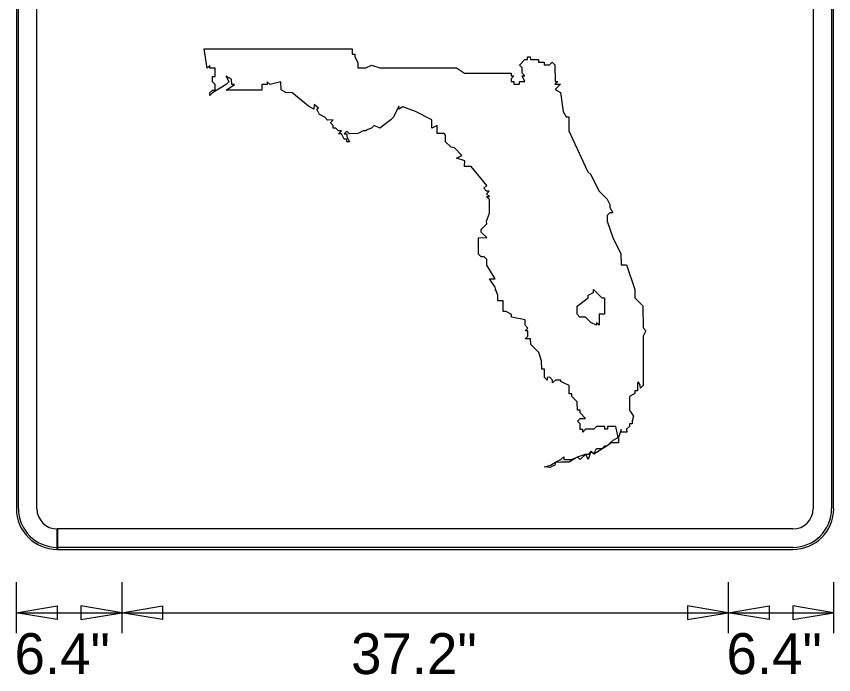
# Model space of a CAD drawing. Extents: x 17890628 to 17890844, y 17897693 to 17898031.
# Drawn here: x 17890743.68 to 17890757.02, y 17897935.63 to 17897946.37 of the extents above; entities that cross this region are included whole.
import ezdxf

# ---------------------------------------------------------------- set-up
doc = ezdxf.new("R2010")
doc.units = 0
doc.layers.add('GSColorFill', color=7, linetype='Continuous')
doc.layers.add('GSDims', color=7, linetype='Continuous')

msp = doc.modelspace()

# ---------------------------------------------------------------- linework, layer by layer
at = {"layer": 'GSColorFill'}
for p, q in [((17890743.684, 17897953.004), (17890743.684, 17897938.337)), ((17890743.684, 17897953.004), (17890743.684, 17897938.337)), ((17890743.684, 17897953.004), (17890743.684, 17897938.337)), ((17890743.717, 17897938.337), (17890743.717, 17897953.004)), ((17890744.017, 17897938.337), (17890744.017, 17897953.004)), ((17890756.684, 17897953.004), (17890756.684, 17897938.337)), ((17890756.984, 17897953.004), (17890756.984, 17897938.337)), ((17890757.017, 17897938.337), (17890757.017, 17897953.004)), ((17890757.017, 17897938.337), (17890757.017, 17897953.004)), ((17890757.017, 17897938.337), (17890757.017, 17897953.004)), ((17890746.75, 17897945.836), (17890749.163, 17897945.839)), ((17890746.794, 17897945.523), (17890746.75, 17897945.836)), ((17890749.163, 17897945.839), (17890749.163, 17897945.75)), ((17890749.163, 17897945.75), (17890749.208, 17897945.749)), ((17890749.208, 17897945.749), (17890749.207, 17897945.705)), ((17890749.207, 17897945.705), (17890749.252, 17897945.616)), ((17890751.89, 17897945.573), (17890751.979, 17897945.663)), ((17890751.979, 17897945.663), (17890752.023, 17897945.663)), ((17890752.023, 17897945.663), (17890752.024, 17897945.708)), ((17890752.024, 17897945.708), (17890752.068, 17897945.708)), ((17890752.068, 17897945.708), (17890752.069, 17897945.663)), ((17890752.069, 17897945.663), (17890752.203, 17897945.663)), ((17890752.203, 17897945.663), (17890752.203, 17897945.619)), ((17890752.203, 17897945.619), (17890752.293, 17897945.619)), ((17890752.293, 17897945.619), (17890752.293, 17897945.575)), ((17890752.381, 17897945.574), (17890752.426, 17897945.619)), ((17890752.426, 17897945.619), (17890752.471, 17897945.574)), ((17890746.839, 17897945.567), (17890746.794, 17897945.523)), ((17890746.838, 17897945.523), (17890746.839, 17897945.567)), ((17890746.928, 17897945.524), (17890746.838, 17897945.523)), ((17890746.928, 17897945.389), (17890746.928, 17897945.524)), ((17890749.252, 17897945.616), (17890749.252, 17897945.526)), ((17890749.252, 17897945.526), (17890749.387, 17897945.527)), ((17890749.387, 17897945.527), (17890749.477, 17897945.571)), ((17890749.477, 17897945.571), (17890749.611, 17897945.527)), ((17890749.611, 17897945.527), (17890750.862, 17897945.529)), ((17890750.862, 17897945.529), (17890750.996, 17897945.439)), ((17890751.935, 17897945.529), (17890751.89, 17897945.573)), ((17890751.935, 17897945.44), (17890751.935, 17897945.529)), ((17890752.293, 17897945.575), (17890752.381, 17897945.574)), ((17890752.471, 17897945.574), (17890752.472, 17897945.307)), ((17890746.884, 17897945.3), (17890746.883, 17897945.389)), ((17890746.883, 17897945.389), (17890746.928, 17897945.389)), ((17890747.196, 17897945.345), (17890747.107, 17897945.39)), ((17890747.107, 17897945.39), (17890747.152, 17897945.3)), ((17890750.996, 17897945.439), (17890751.756, 17897945.44)), ((17890751.756, 17897945.44), (17890751.756, 17897945.395)), ((17890751.756, 17897945.395), (17890751.801, 17897945.395)), ((17890751.801, 17897945.395), (17890751.756, 17897945.351)), ((17890751.979, 17897945.395), (17890751.935, 17897945.44)), ((17890751.979, 17897945.305), (17890751.935, 17897945.396)), ((17890751.935, 17897945.396), (17890751.979, 17897945.395)), ((17890746.928, 17897945.255), (17890746.884, 17897945.3)), ((17890747.107, 17897945.256), (17890746.884, 17897945.121)), ((17890746.929, 17897945.166), (17890746.928, 17897945.255)), ((17890747.152, 17897945.3), (17890747.107, 17897945.256)), ((17890747.108, 17897945.166), (17890747.241, 17897945.256)), ((17890747.197, 17897945.256), (17890747.196, 17897945.345)), ((17890747.241, 17897945.256), (17890747.197, 17897945.256)), ((17890747.778, 17897945.256), (17890747.688, 17897945.256)), ((17890747.688, 17897945.256), (17890747.689, 17897945.166)), ((17890747.822, 17897945.256), (17890747.777, 17897945.301)), ((17890747.777, 17897945.301), (17890747.778, 17897945.256)), ((17890748.001, 17897945.301), (17890747.822, 17897945.256)), ((17890748.002, 17897945.167), (17890748.001, 17897945.301)), ((17890751.756, 17897945.351), (17890751.756, 17897945.305)), ((17890751.756, 17897945.305), (17890751.801, 17897945.305)), ((17890751.801, 17897945.305), (17890751.801, 17897945.261)), ((17890751.801, 17897945.261), (17890751.89, 17897945.261)), ((17890751.89, 17897945.261), (17890751.891, 17897945.306)), ((17890751.891, 17897945.306), (17890751.979, 17897945.305)), ((17890752.516, 17897945.306), (17890752.471, 17897945.262)), ((17890752.471, 17897945.262), (17890752.561, 17897945.262)), ((17890752.472, 17897945.307), (17890752.516, 17897945.306)), ((17890752.561, 17897945.262), (17890752.472, 17897945.173)), ((17890746.839, 17897945.121), (17890746.884, 17897945.166)), ((17890746.884, 17897945.121), (17890746.839, 17897945.077)), ((17890746.839, 17897945.077), (17890746.839, 17897945.121)), ((17890746.884, 17897945.166), (17890746.929, 17897945.166)), ((17890747.689, 17897945.166), (17890747.108, 17897945.166)), ((17890748.092, 17897945.122), (17890748.002, 17897945.167)), ((17890748.18, 17897945.123), (17890748.092, 17897945.122)), ((17890748.449, 17897944.9), (17890748.18, 17897945.123)), ((17890752.472, 17897945.173), (17890752.561, 17897945.128)), ((17890752.561, 17897945.128), (17890752.607, 17897944.815)), ((17890748.539, 17897944.854), (17890748.449, 17897944.9)), ((17890748.542, 17897944.93), (17890748.539, 17897944.854)), ((17890748.612, 17897944.869), (17890748.542, 17897944.93)), ((17890748.583, 17897944.854), (17890748.612, 17897944.869)), ((17890748.627, 17897944.765), (17890748.583, 17897944.854)), ((17890749.924, 17897944.901), (17890749.835, 17897944.723)), ((17890749.924, 17897944.856), (17890749.924, 17897944.901)), ((17890749.988, 17897944.889), (17890749.924, 17897944.856)), ((17890750.193, 17897944.813), (17890749.988, 17897944.889)), ((17890748.718, 17897944.721), (17890748.627, 17897944.765)), ((17890748.762, 17897944.676), (17890748.718, 17897944.721)), ((17890749.835, 17897944.723), (17890749.791, 17897944.678)), ((17890750.461, 17897944.678), (17890750.193, 17897944.813)), ((17890752.607, 17897944.815), (17890752.651, 17897944.726)), ((17890752.651, 17897944.726), (17890752.696, 17897944.726)), ((17890752.696, 17897944.726), (17890752.696, 17897944.502)), ((17890748.851, 17897944.677), (17890748.762, 17897944.676)), ((17890748.806, 17897944.632), (17890748.851, 17897944.677)), ((17890748.852, 17897944.587), (17890748.806, 17897944.632)), ((17890748.852, 17897944.543), (17890748.852, 17897944.587)), ((17890749.522, 17897944.588), (17890749.478, 17897944.543)), ((17890749.611, 17897944.543), (17890749.522, 17897944.588)), ((17890749.791, 17897944.678), (17890749.611, 17897944.543)), ((17890750.461, 17897944.545), (17890750.461, 17897944.678)), ((17890750.55, 17897944.589), (17890750.461, 17897944.545)), ((17890750.551, 17897944.455), (17890750.55, 17897944.589)), ((17890748.896, 17897944.542), (17890748.852, 17897944.543)), ((17890748.941, 17897944.498), (17890748.896, 17897944.542)), ((17890748.94, 17897944.453), (17890748.986, 17897944.498)), ((17890748.986, 17897944.453), (17890748.94, 17897944.453)), ((17890748.986, 17897944.498), (17890748.941, 17897944.498)), ((17890749.031, 17897944.364), (17890748.986, 17897944.453)), ((17890749.075, 17897944.497), (17890749.03, 17897944.452)), ((17890749.03, 17897944.452), (17890749.074, 17897944.452)), ((17890749.074, 17897944.452), (17890749.075, 17897944.407)), ((17890749.119, 17897944.453), (17890749.075, 17897944.497)), ((17890749.253, 17897944.454), (17890749.119, 17897944.453)), ((17890749.343, 17897944.498), (17890749.253, 17897944.454)), ((17890749.388, 17897944.498), (17890749.343, 17897944.498)), ((17890749.478, 17897944.543), (17890749.388, 17897944.513)), ((17890749.388, 17897944.513), (17890749.388, 17897944.498)), ((17890750.664, 17897944.455), (17890750.551, 17897944.455)), ((17890750.685, 17897944.43), (17890750.664, 17897944.455)), ((17890750.685, 17897944.321), (17890750.685, 17897944.43)), ((17890752.696, 17897944.502), (17890752.965, 17897943.922)), ((17890749.075, 17897944.363), (17890749.031, 17897944.364)), ((17890749.075, 17897944.407), (17890749.119, 17897944.319)), ((17890749.076, 17897944.323), (17890749.075, 17897944.363)), ((17890749.119, 17897944.319), (17890749.076, 17897944.323)), ((17890750.775, 17897944.232), (17890750.685, 17897944.321)), ((17890750.829, 17897944.222), (17890750.775, 17897944.232)), ((17890750.953, 17897944.098), (17890750.829, 17897944.222)), ((17890750.864, 17897944.052), (17890750.953, 17897944.098)), ((17890750.998, 17897944.008), (17890750.864, 17897944.052)), ((17890750.997, 17897943.919), (17890750.998, 17897944.008)), ((17890751.104, 17897943.919), (17890750.997, 17897943.919)), ((17890751.359, 17897943.609), (17890751.104, 17897943.919)), ((17890752.965, 17897943.922), (17890753.009, 17897943.831)), ((17890753.009, 17897943.831), (17890753.056, 17897943.787)), ((17890753.056, 17897943.787), (17890753.189, 17897943.519)), ((17890751.311, 17897943.562), (17890751.359, 17897943.609)), ((17890751.355, 17897943.518), (17890751.311, 17897943.562)), ((17890751.399, 17897943.515), (17890751.355, 17897943.518)), ((17890751.356, 17897943.473), (17890751.399, 17897943.515)), ((17890753.189, 17897943.519), (17890753.323, 17897943.385)), ((17890751.401, 17897943.428), (17890751.356, 17897943.473)), ((17890751.401, 17897943.382), (17890751.356, 17897943.428)), ((17890751.356, 17897943.428), (17890751.364, 17897943.427)), ((17890751.364, 17897943.427), (17890751.401, 17897943.428)), ((17890751.401, 17897943.159), (17890751.401, 17897943.382)), ((17890753.323, 17897943.385), (17890753.367, 17897943.296)), ((17890753.367, 17897943.296), (17890753.368, 17897943.251)), ((17890753.368, 17897943.251), (17890753.413, 17897943.161)), ((17890751.356, 17897943.025), (17890751.401, 17897943.159)), ((17890753.368, 17897943.162), (17890753.323, 17897943.117)), ((17890753.323, 17897943.117), (17890753.323, 17897943.028)), ((17890753.413, 17897943.161), (17890753.368, 17897943.162)), ((17890751.268, 17897942.891), (17890751.357, 17897942.98)), ((17890751.357, 17897942.98), (17890751.356, 17897943.025)), ((17890753.323, 17897943.028), (17890753.413, 17897942.759)), ((17890751.267, 17897942.847), (17890751.268, 17897942.891)), ((17890751.358, 17897942.757), (17890751.267, 17897942.847)), ((17890751.223, 17897942.756), (17890751.358, 17897942.757)), ((17890751.223, 17897942.489), (17890751.223, 17897942.756)), ((17890753.413, 17897942.759), (17890753.547, 17897942.492)), ((17890751.268, 17897942.444), (17890751.223, 17897942.489)), ((17890751.313, 17897942.444), (17890751.268, 17897942.444)), ((17890751.358, 17897942.4), (17890751.313, 17897942.444)), ((17890753.547, 17897942.492), (17890753.548, 17897942.312)), ((17890751.358, 17897942.31), (17890751.358, 17897942.4)), ((17890751.493, 17897942.086), (17890751.358, 17897942.31)), ((17890753.548, 17897942.312), (17890753.637, 17897942.313)), ((17890753.637, 17897942.313), (17890753.771, 17897941.91)), ((17890751.493, 17897941.952), (17890751.402, 17897942.086)), ((17890751.402, 17897942.086), (17890751.493, 17897942.086)), ((17890751.513, 17897941.887), (17890751.492, 17897941.908)), ((17890751.492, 17897941.908), (17890751.507, 17897941.908)), ((17890751.507, 17897941.908), (17890751.493, 17897941.952)), ((17890751.537, 17897941.818), (17890751.513, 17897941.887)), ((17890753.771, 17897941.91), (17890753.772, 17897941.777)), ((17890751.538, 17897941.728), (17890751.537, 17897941.818)), ((17890753.772, 17897941.777), (17890753.906, 17897941.643)), ((17890751.627, 17897941.729), (17890751.538, 17897941.728)), ((17890751.627, 17897941.55), (17890751.627, 17897941.729)), ((17890753.906, 17897941.643), (17890753.907, 17897941.285)), ((17890751.673, 17897941.55), (17890751.627, 17897941.55)), ((17890751.761, 17897941.506), (17890751.673, 17897941.55)), ((17890751.761, 17897941.461), (17890751.761, 17897941.506)), ((17890751.984, 17897941.417), (17890751.761, 17897941.461)), ((17890751.985, 17897941.327), (17890751.984, 17897941.417)), ((17890751.984, 17897941.238), (17890752.028, 17897941.283)), ((17890752.029, 17897941.238), (17890751.984, 17897941.238)), ((17890752.028, 17897941.283), (17890751.985, 17897941.327)), ((17890752.03, 17897941.149), (17890752.029, 17897941.238)), ((17890753.907, 17897941.285), (17890753.951, 17897941.239)), ((17890753.951, 17897941.239), (17890753.908, 17897941.15)), ((17890751.984, 17897941.104), (17890752.03, 17897941.149)), ((17890752.074, 17897941.104), (17890751.984, 17897941.104)), ((17890752.075, 17897941.015), (17890752.074, 17897941.104)), ((17890753.908, 17897941.15), (17890753.909, 17897940.346)), ((17890752.208, 17897940.881), (17890752.075, 17897941.015)), ((17890752.253, 17897940.747), (17890752.208, 17897940.881)), ((17890752.254, 17897940.612), (17890752.253, 17897940.747)), ((17890752.298, 17897940.612), (17890752.254, 17897940.612)), ((17890752.299, 17897940.478), (17890752.298, 17897940.612)), ((17890752.343, 17897940.434), (17890752.299, 17897940.478)), ((17890752.344, 17897940.478), (17890752.343, 17897940.434)), ((17890752.388, 17897940.479), (17890752.344, 17897940.478)), ((17890752.433, 17897940.434), (17890752.388, 17897940.479)), ((17890752.477, 17897940.434), (17890752.433, 17897940.389)), ((17890752.433, 17897940.389), (17890752.433, 17897940.434)), ((17890752.567, 17897940.434), (17890752.477, 17897940.434)), ((17890752.567, 17897940.411), (17890752.567, 17897940.434)), ((17890752.611, 17897940.389), (17890752.567, 17897940.411)), ((17890752.701, 17897940.345), (17890752.611, 17897940.389)), ((17890752.701, 17897940.21), (17890752.701, 17897940.345)), ((17890753.819, 17897940.391), (17890753.818, 17897940.256)), ((17890753.834, 17897940.405), (17890753.819, 17897940.391)), ((17890753.863, 17897940.347), (17890753.834, 17897940.405)), ((17890753.864, 17897940.301), (17890753.863, 17897940.347)), ((17890753.909, 17897940.346), (17890753.864, 17897940.301)), ((17890752.746, 17897940.21), (17890752.701, 17897940.21)), ((17890752.746, 17897940.166), (17890752.746, 17897940.21)), ((17890752.835, 17897940.076), (17890752.746, 17897940.166)), ((17890753.774, 17897940.212), (17890753.684, 17897940.167)), ((17890753.684, 17897940.167), (17890753.685, 17897939.943)), ((17890753.818, 17897940.256), (17890753.774, 17897940.256)), ((17890753.774, 17897940.256), (17890753.774, 17897940.212)), ((17890752.836, 17897939.942), (17890752.835, 17897940.076)), ((17890752.881, 17897939.94), (17890752.836, 17897939.942)), ((17890752.882, 17897939.898), (17890752.881, 17897939.94)), ((17890752.97, 17897939.808), (17890752.882, 17897939.898)), ((17890753.685, 17897939.943), (17890753.751, 17897939.845)), ((17890752.836, 17897939.764), (17890752.881, 17897939.809)), ((17890752.88, 17897939.719), (17890752.836, 17897939.764)), ((17890752.881, 17897939.809), (17890752.97, 17897939.808)), ((17890753.751, 17897939.845), (17890753.73, 17897939.765)), ((17890753.73, 17897939.765), (17890753.73, 17897939.72)), ((17890752.881, 17897939.629), (17890752.88, 17897939.719)), ((17890752.926, 17897939.629), (17890752.881, 17897939.629)), ((17890752.97, 17897939.63), (17890752.926, 17897939.585)), ((17890752.926, 17897939.585), (17890752.926, 17897939.629)), ((17890753.105, 17897939.63), (17890752.97, 17897939.63)), ((17890753.149, 17897939.675), (17890753.105, 17897939.63)), ((17890753.283, 17897939.675), (17890753.149, 17897939.675)), ((17890753.283, 17897939.63), (17890753.283, 17897939.675)), ((17890753.328, 17897939.631), (17890753.283, 17897939.63)), ((17890753.462, 17897939.675), (17890753.328, 17897939.675)), ((17890753.328, 17897939.675), (17890753.328, 17897939.631)), ((17890753.502, 17897939.497), (17890753.462, 17897939.675)), ((17890753.552, 17897939.628), (17890753.507, 17897939.497)), ((17890753.551, 17897939.585), (17890753.552, 17897939.628)), ((17890753.686, 17897939.675), (17890753.64, 17897939.631)), ((17890753.64, 17897939.631), (17890753.641, 17897939.586)), ((17890753.73, 17897939.72), (17890753.684, 17897939.72)), ((17890753.684, 17897939.72), (17890753.686, 17897939.675)), ((17890753.418, 17897939.452), (17890753.502, 17897939.497)), ((17890753.507, 17897939.497), (17890753.507, 17897939.407)), ((17890753.641, 17897939.586), (17890753.551, 17897939.585)), ((17890753.323, 17897939.359), (17890753.105, 17897939.227)), ((17890753.239, 17897939.317), (17890753.284, 17897939.362)), ((17890753.284, 17897939.362), (17890753.326, 17897939.364)), ((17890753.389, 17897939.407), (17890753.323, 17897939.359)), ((17890753.326, 17897939.364), (17890753.372, 17897939.407)), ((17890753.372, 17897939.407), (17890753.418, 17897939.452)), ((17890753.507, 17897939.407), (17890753.389, 17897939.407)), ((17890752.836, 17897939.183), (17890752.971, 17897939.227)), ((17890752.972, 17897939.225), (17890752.881, 17897939.138)), ((17890752.971, 17897939.227), (17890753.016, 17897939.227)), ((17890753.015, 17897939.138), (17890752.972, 17897939.225)), ((17890753.057, 17897939.267), (17890753.015, 17897939.138)), ((17890753.016, 17897939.227), (17890753.06, 17897939.272)), ((17890753.105, 17897939.227), (17890753.057, 17897939.267)), ((17890753.06, 17897939.272), (17890753.105, 17897939.229)), ((17890753.105, 17897939.229), (17890753.149, 17897939.317)), ((17890753.149, 17897939.317), (17890753.239, 17897939.317)), ((17890752.396, 17897939.043), (17890752.479, 17897939.093)), ((17890752.48, 17897939.091), (17890752.469, 17897939.044)), ((17890752.479, 17897939.093), (17890752.568, 17897939.138)), ((17890752.569, 17897939.093), (17890752.48, 17897939.091)), ((17890752.568, 17897939.138), (17890752.613, 17897939.182)), ((17890752.703, 17897939.094), (17890752.569, 17897939.093)), ((17890752.613, 17897939.182), (17890752.613, 17897939.137)), ((17890752.613, 17897939.137), (17890752.746, 17897939.137)), ((17890752.803, 17897939.158), (17890752.703, 17897939.094)), ((17890752.746, 17897939.137), (17890752.836, 17897939.183)), ((17890752.846, 17897939.174), (17890752.803, 17897939.158)), ((17890752.881, 17897939.138), (17890752.846, 17897939.174)), ((17890752.295, 17897939.019), (17890752.344, 17897939.027)), ((17890752.391, 17897939.005), (17890752.295, 17897939.019)), ((17890752.344, 17897939.027), (17890752.396, 17897939.043)), ((17890752.428, 17897939.027), (17890752.391, 17897939.005)), ((17890752.469, 17897939.044), (17890752.428, 17897939.027)), ((17890744.351, 17897937.67), (17890744.351, 17897938.004)), ((17890756.351, 17897938.004), (17890744.354, 17897938.004)), ((17890744.354, 17897938.004), (17890744.354, 17897937.67)), ((17890744.351, 17897937.67), (17890744.351, 17897937.704)), ((17890756.351, 17897937.704), (17890744.351, 17897937.704)), ((17890744.351, 17897937.704), (17890744.351, 17897937.67)), ((17890744.351, 17897937.67), (17890756.351, 17897937.67)), ((17890744.351, 17897937.67), (17890756.351, 17897937.67)), ((17890744.354, 17897937.67), (17890756.351, 17897937.67))]:
    msp.add_line(p, q, dxfattribs=at)
msp.add_lwpolyline([(17890753.101, 17897941.909), (17890753.236, 17897941.776), (17890753.28, 17897941.775), (17890753.281, 17897941.507), (17890753.191, 17897941.508), (17890753.191, 17897941.329), (17890753.147, 17897941.373), (17890753.147, 17897941.328), (17890753.058, 17897941.373), (17890752.968, 17897941.462), (17890752.879, 17897941.462), (17890752.834, 17897941.507), (17890752.835, 17897941.642), (17890753.013, 17897941.775), (17890753.012, 17897941.82), (17890753.101, 17897941.865)], close=True, dxfattribs=at)
for centre, radius, start, end in [((17890744.351, 17897938.337), 0.667, 180, 270), ((17890744.351, 17897938.337), 0.667, 180, 270), ((17890744.351, 17897938.337), 0.667, 180, 270), ((17890744.351, 17897938.337), 0.633, 180, 270), ((17890744.351, 17897938.337), 0.333, 180, 270), ((17890756.351, 17897938.337), 0.667, 270, 0), ((17890756.351, 17897938.337), 0.667, 270, 0), ((17890756.351, 17897938.337), 0.333, 270, 360), ((17890756.351, 17897938.337), 0.667, 270, 0), ((17890756.351, 17897938.337), 0.633, 270, 0)]:
    msp.add_arc(centre, radius, start, end, dxfattribs=at)
at = {"layer": 'GSDims'}
for p, q in [((17890743.683, 17897937.137), (17890743.683, 17897936.304)), ((17890745.402, 17897937.137), (17890745.402, 17897936.304)), ((17890745.402, 17897937.137), (17890745.402, 17897936.304)), ((17890755.298, 17897937.137), (17890755.298, 17897936.304)), ((17890755.298, 17897937.137), (17890755.298, 17897936.304)), ((17890757.017, 17897937.137), (17890757.017, 17897936.304)), ((17890743.683, 17897936.637), (17890745.402, 17897936.637)), ((17890745.402, 17897936.637), (17890755.298, 17897936.637)), ((17890755.298, 17897936.637), (17890757.017, 17897936.637))]:
    msp.add_line(p, q, dxfattribs=at)
for points in [[(17890743.683, 17897936.637), (17890744.35, 17897936.748), (17890744.35, 17897936.526)], [(17890745.402, 17897936.637), (17890744.736, 17897936.748), (17890744.736, 17897936.526)], [(17890745.402, 17897936.637), (17890746.069, 17897936.748), (17890746.069, 17897936.526)], [(17890755.298, 17897936.637), (17890754.631, 17897936.748), (17890754.631, 17897936.526)], [(17890755.298, 17897936.637), (17890755.965, 17897936.748), (17890755.965, 17897936.526)], [(17890757.017, 17897936.637), (17890756.35, 17897936.748), (17890756.35, 17897936.526)]]:
    msp.add_lwpolyline(points, close=True, dxfattribs=at)

# ---------------------------------------------------------------- texts
for s, p in [('6.4"', (17890743.654, 17897935.637)), ('37.2"', (17890749.144, 17897935.637)), ('6.4"', (17890755.269, 17897935.637))]:
    msp.add_text(s, height=0.6667, dxfattribs=at).set_placement(p)

doc.saveas('drawing.dxf')
